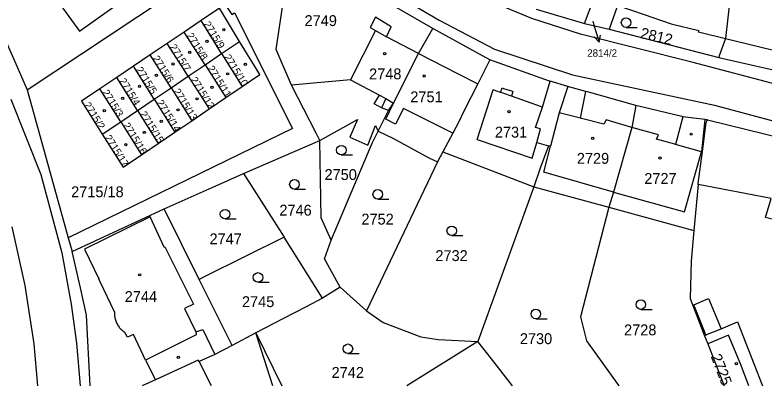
# Model space of a CAD drawing. Extents: x -527335 to -526256, y -1079142 to -1077836.
# Drawn here: x -527116.6 to -526999.4, y -1079141.5 to -1079083.6 of the extents above; entities that cross this region are included whole.
import ezdxf

# ---------------------------------------------------------------- set-up
doc = ezdxf.new("R2010")
doc.units = 0
for name, color, linetype in [('Hranice parcel', 7, 'Continuous'), ('Parcelní čísla', 7, 'Continuous'), ('Pop  PČ popisy', 7, 'Continuous'), ('Vnitřní kresba', 7, 'Continuous'), ('Značky budov', 7, 'Continuous'), ('Značky kultur', 7, 'Continuous')]:
    doc.layers.add(name, color=color, linetype=linetype)

msp = doc.modelspace()

# ---------------------------------------------------------------- linework, layer by layer
at = {"layer": 'Hranice parcel'}
for p, q in [((-527027.56, -1079084.87), (-527026.14, -1079080.97)), ((-527035.15, -1079082.66), (-527027.56, -1079084.87)), ((-527022.5, -1079082.36), (-527023.73, -1079085.78)), ((-527087.52, -1079084.42), (-527090.18, -1079086.21)), ((-527084.33, -1079089.58), (-527087.52, -1079084.42)), ((-527027.56, -1079084.87), (-527023.73, -1079085.78)), ((-527090.18, -1079086.21), (-527092.83, -1079087.99)), ((-527086.93, -1079091.34), (-527090.18, -1079086.21)), ((-527053.53, -1079089.58), (-527051.3, -1079085.65)), ((-527042.41, -1079090.54), (-527051.3, -1079085.65)), ((-527023.73, -1079085.78), (-527006.59, -1079090.18)), ((-527084.33, -1079089.58), (-527081.51, -1079087.68)), ((-527092.83, -1079087.99), (-527095.49, -1079089.78)), ((-527089.56, -1079093.11), (-527092.83, -1079087.99)), ((-527095.49, -1079089.78), (-527098.1, -1079091.54)), ((-527092.24, -1079094.93), (-527095.49, -1079089.78)), ((-527086.93, -1079091.34), (-527084.33, -1079089.58)), ((-527084.33, -1079089.58), (-527081.13, -1079094.75)), ((-527089.56, -1079093.11), (-527086.93, -1079091.34)), ((-527086.93, -1079091.34), (-527083.68, -1079096.47)), ((-527098.1, -1079091.54), (-527100.72, -1079093.3)), ((-527094.86, -1079096.7), (-527098.1, -1079091.54)), ((-527100.72, -1079093.3), (-527103.37, -1079095.09)), ((-527097.49, -1079098.47), (-527100.72, -1079093.3)), ((-527092.24, -1079094.93), (-527089.56, -1079093.11)), ((-527089.56, -1079093.11), (-527086.28, -1079098.23)), ((-527083.68, -1079096.47), (-527081.13, -1079094.75)), ((-527114.75, -1079095.26), (-527108.32, -1079118.4)), ((-527100.12, -1079100.24), (-527103.37, -1079095.09)), ((-527094.86, -1079096.7), (-527092.24, -1079094.93)), ((-527092.24, -1079094.93), (-527089, -1079100.07)), ((-527097.49, -1079098.47), (-527094.86, -1079096.7)), ((-527094.86, -1079096.7), (-527091.63, -1079101.85)), ((-527086.28, -1079098.23), (-527083.68, -1079096.47)), ((-527089, -1079100.07), (-527086.28, -1079098.23)), ((-527100.12, -1079100.24), (-527097.49, -1079098.47)), ((-527097.49, -1079098.47), (-527094.26, -1079103.63)), ((-527102.99, -1079102.18), (-527100.12, -1079100.24)), ((-527100.12, -1079100.24), (-527096.87, -1079105.39)), ((-527091.63, -1079101.85), (-527089, -1079100.07)), ((-527094.26, -1079103.63), (-527091.63, -1079101.85)), ((-527096.87, -1079105.39), (-527094.26, -1079103.63)), ((-527080.91, -1079108.31), (-527068.95, -1079103.19)), ((-527049.72, -1079104.95), (-527050.56, -1079106.52)), ((-527049.72, -1079104.95), (-527035.52, -1079110.39)), ((-527050.56, -1079106.52), (-527061.66, -1079129.77)), ((-527080.91, -1079108.31), (-527074.57, -1079118.3)), ((-527009.82, -1079110.06), (-527010.5, -1079117.24)), ((-527035.52, -1079110.39), (-527044.28, -1079134.58)), ((-527035.52, -1079110.39), (-527023.76, -1079113.6)), ((-527023.76, -1079113.6), (-527010.5, -1079117.24)), ((-527107.73, -1079120.51), (-527093.31, -1079113.86)), ((-527087.83, -1079124.87), (-527093.31, -1079113.86)), ((-527068.54, -1079127.79), (-527074.57, -1079118.3)), ((-527108.32, -1079118.4), (-527107.73, -1079120.51)), ((-527082.7, -1079135.19), (-527087.83, -1079124.87)), ((-527065.77, -1079126.11), (-527068.54, -1079127.79)), ((-527061.66, -1079129.77), (-527065.77, -1079126.11)), ((-527078.96, -1079133.24), (-527082.7, -1079135.19)), ((-527076.3, -1079141.53), (-527078.96, -1079133.24)), ((-527078.96, -1079133.24), (-527074.91, -1079141.53)), ((-527044.28, -1079134.58), (-527055.39, -1079141.53)), ((-527042.15, -1079137.3), (-527044.28, -1079134.58)), ((-527008.8, -1079133.68), (-527008.31, -1079134.94)), ((-527008.31, -1079134.94), (-527005.73, -1079141.53)), ((-527038.84, -1079141.53), (-527042.15, -1079137.3))]:
    msp.add_line(p, q, dxfattribs=at)
for points in [[(-527175.94, -1079018.95), (-527174.51, -1079020.99), (-527170.88, -1079024.19), (-527166.19, -1079028.15), (-527156.94, -1079036.03), (-527151.99, -1079040.51), (-527144.47, -1079048.33), (-527131.02, -1079065.08), (-527128.12, -1079070.27), (-527126.15, -1079072.81), (-527121.46, -1079080.6), (-527119.15, -1079085.27), (-527115.79, -1079092.86), (-527114.75, -1079095.26)], [(-527117.52, -1079070.91), (-527112.81, -1079077.42), (-527111.7, -1079078.95), (-527106.54, -1079086.08), (-527097.38, -1079079.49), (-527102.75, -1079072.09), (-527104.98, -1079069.03), (-527108.4, -1079064.32), (-527113.48, -1079057.33), (-527115.7, -1079054.27), (-527119.42, -1079049.14)], [(-527017.49, -1079069.84), (-527011.34, -1079074.38), (-527006.77, -1079078.58), (-527004.82, -1079080.69), (-527005.52, -1079087.25)], [(-527073.4, -1079094.53), (-527075.8, -1079088.93), (-527073.64, -1079074.56), (-527071.09, -1079071.9)], [(-527051.3, -1079085.65), (-527059.51, -1079080.86), (-527065.39, -1079076.64), (-527071.09, -1079071.9)], [(-527114.75, -1079095.26), (-527093.11, -1079080.89), (-527091.79, -1079079.94), (-527087.05, -1079076.88), (-527082.75, -1079083.47), (-527082.32, -1079083.22), (-527073.26, -1079101.27), (-527108.32, -1079118.4)], [(-527081.51, -1079087.68), (-527084.66, -1079082.49), (-527087.52, -1079084.42)], [(-527022.39, -1079082.06), (-527018.27, -1079083.48), (-527014.05, -1079084.93), (-527009.72, -1079085.95), (-527009.78, -1079086.18), (-527009.52, -1079086.24), (-527005.52, -1079087.25)], [(-527053.53, -1079089.58), (-527058.56, -1079086.96), (-527057.82, -1079085.39), (-527060.29, -1079083.91), (-527061.12, -1079085.5), (-527060.26, -1079085.95), (-527064.15, -1079093.71), (-527073.4, -1079094.53)], [(-527081.13, -1079094.75), (-527078.36, -1079092.87), (-527081.51, -1079087.68)], [(-527005.52, -1079087.25), (-527006.5, -1079089.94), (-527006.59, -1079090.18)], [(-527059.85, -1079101.72), (-527058.21, -1079098.49), (-527057.45, -1079097.35), (-527053.53, -1079089.58)], [(-527006.59, -1079090.18), (-526994.63, -1079092.92), (-526991.9, -1079089.68)], [(-527042.41, -1079090.54), (-527044.26, -1079094.33), (-527046.46, -1079098.6), (-527047.21, -1079100.23), (-527048.16, -1079102.02), (-527049.72, -1079104.95)], [(-527030.16, -1079094.72), (-527032.95, -1079093.92), (-527033.07, -1079093.88), (-527042.41, -1079090.54)], [(-527068.95, -1079103.19), (-527069.52, -1079102.03), (-527073.4, -1079094.53)], [(-527030.16, -1079094.72), (-527031.52, -1079098.85), (-527032.88, -1079104.05), (-527033.22, -1079104), (-527034.51, -1079107.51), (-527035.52, -1079110.39)], [(-527019.56, -1079097.69), (-527027.13, -1079095.57), (-527027.36, -1079095.5), (-527030.01, -1079094.76), (-527030.16, -1079094.72)], [(-527103.37, -1079095.09), (-527106.24, -1079097.02), (-527102.99, -1079102.18)], [(-527019.56, -1079097.69), (-527020.17, -1079101.16), (-527023.05, -1079111.23), (-527023.76, -1079113.6)], [(-527008.36, -1079099.95), (-527008.58, -1079099.92), (-527008.77, -1079099.9), (-527012.21, -1079099.46), (-527012.36, -1079099.44), (-527019.56, -1079097.69)], [(-527068.95, -1079103.19), (-527063.07, -1079099.9), (-527064.28, -1079102.63), (-527061.45, -1079103.88), (-527060.28, -1079100.83), (-527059.85, -1079101.72)], [(-527009.82, -1079110.06), (-527009.8, -1079109.91), (-527009.1, -1079104.91), (-527008.55, -1079100.34), (-527008.36, -1079099.95)], [(-527008.36, -1079099.95), (-526996.25, -1079102.89), (-526987.44, -1079105.14), (-526984.58, -1079106.98)], [(-527067.18, -1079118.75), (-527060.79, -1079103.58), (-527059.85, -1079101.72)], [(-527059.85, -1079101.72), (-527057.47, -1079102.88), (-527051.9, -1079105.88), (-527050.56, -1079106.52)], [(-527102.99, -1079102.18), (-527099.75, -1079107.33), (-527096.87, -1079105.39)], [(-527067.18, -1079118.75), (-527068.78, -1079115.24), (-527068.95, -1079103.19)], [(-527093.31, -1079113.86), (-527085.79, -1079110.53), (-527080.91, -1079108.31)], [(-526971.93, -1079115.94), (-526976.33, -1079115.57), (-526988.12, -1079117.78), (-526988.51, -1079117.72), (-526989.62, -1079117.54), (-526999.27, -1079115.18), (-526998.37, -1079112.24), (-527009.82, -1079110.06)], [(-527023.76, -1079113.6), (-527028.19, -1079130.73), (-527027.25, -1079134.48), (-527022.21, -1079141.53)], [(-527074.57, -1079118.3), (-527086.94, -1079124.43), (-527087.83, -1079124.87)], [(-527010.5, -1079117.24), (-527010.9, -1079122.03), (-527011.07, -1079127.87), (-527008.8, -1079133.68)], [(-527065.77, -1079126.11), (-527068.26, -1079121.64), (-527067.18, -1079118.75)], [(-527104.87, -1079141.53), (-527105.47, -1079130.49), (-527106.38, -1079126.22), (-527107.73, -1079120.51)], [(-527068.54, -1079127.79), (-527071.12, -1079129.14), (-527074.77, -1079131.05), (-527078.96, -1079133.24)], [(-527061.66, -1079129.77), (-527059.09, -1079131.59), (-527053.17, -1079133.84), (-527050.44, -1079134.25), (-527044.28, -1079134.58)], [(-527008.8, -1079133.68), (-527008.59, -1079133.56), (-527006.18, -1079132.58), (-527003.65, -1079131.52), (-526999.76, -1079141.53)], [(-527001.89, -1079141.53), (-527003.17, -1079138.09), (-527005.05, -1079133.57), (-527008.31, -1079134.94)], [(-527082.7, -1079135.19), (-527085.39, -1079136.6), (-527087.84, -1079137.7), (-527088, -1079137.51), (-527094.65, -1079140.58), (-527096.75, -1079141.53)]]:
    msp.add_lwpolyline(points, dxfattribs=at)
at = {"layer": 'Pop  PČ popisy'}
for p, q in [((-527026.27, -1079084.53), (-527026.16, -1079084.91)), ((-527026.16, -1079084.91), (-527025.28, -1079087.78)), ((-527025.28, -1079087.78), (-527026.05, -1079086.97)), ((-527025.28, -1079087.78), (-527025.1, -1079086.68))]:
    msp.add_line(p, q, dxfattribs=at)
at = {"layer": 'Vnitřní kresba'}
for p, q in [((-527058.51, -1079079.53), (-527050.31, -1079084.34)), ((-527035.83, -1079084.12), (-527043.03, -1079081.09)), ((-527028.2, -1079086.55), (-527035.83, -1079084.12)), ((-527050.31, -1079084.34), (-527041.68, -1079088.91)), ((-527060.26, -1079085.95), (-527058.56, -1079086.96)), ((-527010.79, -1079090.93), (-527028.2, -1079086.55)), ((-527005.52, -1079087.25), (-526998.21, -1079088.98)), ((-527041.68, -1079088.91), (-527029.48, -1079092.89)), ((-527053.53, -1079089.58), (-527047.35, -1079092.75)), ((-526994.16, -1079095.3), (-527010.79, -1079090.93)), ((-527047.35, -1079092.75), (-527044.26, -1079094.33)), ((-527029.48, -1079092.89), (-527007.27, -1079097.63)), ((-527064.15, -1079093.71), (-527059.66, -1079096.06)), ((-527034.16, -1079097.97), (-527032.95, -1079093.92)), ((-527044.36, -1079103.01), (-527041.85, -1079095.25)), ((-527040.71, -1079095.64), (-527041.85, -1079095.25)), ((-527040.71, -1079095.64), (-527040.46, -1079094.96)), ((-527040.46, -1079095.73), (-527040.71, -1079095.64)), ((-527040.46, -1079094.96), (-527040.23, -1079095.03)), ((-527039.29, -1079096.14), (-527040.46, -1079095.73)), ((-527040.23, -1079095.03), (-527039.01, -1079095.42)), ((-527038.77, -1079095.5), (-527039.02, -1079096.23)), ((-527039.01, -1079095.42), (-527038.77, -1079095.5)), ((-527028.22, -1079099.7), (-527027.36, -1079095.5)), ((-527117.32, -1079096.72), (-527112.58, -1079108.47)), ((-527060.45, -1079097.43), (-527059.66, -1079096.06)), ((-527059.66, -1079096.06), (-527058.66, -1079096.58)), ((-527058.66, -1079096.58), (-527059.35, -1079098.07)), ((-527058.66, -1079096.58), (-527057.45, -1079097.35)), ((-527039.02, -1079096.23), (-527039.29, -1079096.14)), ((-527034.3, -1079097.92), (-527039.02, -1079096.23)), ((-527059.35, -1079098.07), (-527060.45, -1079097.43)), ((-527058.21, -1079098.49), (-527059.35, -1079098.07)), ((-527058.65, -1079099.84), (-527057.45, -1079097.35)), ((-527055.88, -1079098.14), (-527057.14, -1079100.6)), ((-527048.16, -1079102.02), (-527055.88, -1079098.14)), ((-527035.22, -1079101.14), (-527034.16, -1079097.97)), ((-527034.3, -1079097.92), (-527034.16, -1079097.97)), ((-527007.27, -1079097.63), (-526996.46, -1079100.53)), ((-527031.35, -1079098.89), (-527031.52, -1079098.85)), ((-527028.22, -1079099.7), (-527031.35, -1079098.89)), ((-527012.21, -1079099.46), (-527013.34, -1079103.8)), ((-527057.14, -1079100.6), (-527058.65, -1079099.84)), ((-527028.07, -1079099.74), (-527028.22, -1079099.7)), ((-527024.55, -1079100.64), (-527028.07, -1079099.74)), ((-527024.19, -1079099.96), (-527024.55, -1079100.64)), ((-527020.17, -1079101.16), (-527024.19, -1079099.96)), ((-527008.77, -1079099.9), (-527009.28, -1079104.94)), ((-527034.45, -1079101.35), (-527035.22, -1079101.14)), ((-527035.06, -1079103.47), (-527034.45, -1079101.35)), ((-527016, -1079102.26), (-527020.17, -1079101.16)), ((-527044.36, -1079103.01), (-527035.77, -1079105.93)), ((-527016.3, -1079102.96), (-527016, -1079102.26)), ((-527013.46, -1079103.76), (-527016.3, -1079102.96)), ((-527035.77, -1079105.93), (-527035.06, -1079103.47)), ((-527035.06, -1079103.47), (-527033.22, -1079104)), ((-527033.92, -1079108.11), (-527032.88, -1079104.05)), ((-527013.34, -1079103.8), (-527013.46, -1079103.76)), ((-527009.28, -1079104.94), (-527013.34, -1079103.8)), ((-527011.92, -1079114.33), (-527009.28, -1079104.94)), ((-527009.28, -1079104.94), (-527009.1, -1079104.91)), ((-527112.58, -1079108.47), (-527109.31, -1079120.7)), ((-527023.05, -1079111.23), (-527033.92, -1079108.11)), ((-527023.05, -1079111.23), (-527011.92, -1079114.33)), ((-527095.53, -1079115.09), (-527105.76, -1079120.14)), ((-527093.31, -1079119.84), (-527095.53, -1079115.09)), ((-527115.04, -1079125.83), (-527117.11, -1079116.67)), ((-527105.76, -1079120.14), (-527103.56, -1079124.79)), ((-527093.31, -1079119.84), (-527093.19, -1079119.8)), ((-527093.19, -1079119.8), (-527088.74, -1079128.74)), ((-527109.31, -1079120.7), (-527107.85, -1079128.75)), ((-527103.34, -1079125.25), (-527103.56, -1079124.79)), ((-527101.06, -1079129.97), (-527103.34, -1079125.25)), ((-527113.64, -1079134.93), (-527115.04, -1079125.83)), ((-527107.85, -1079128.75), (-527107.02, -1079134.86)), ((-527088.74, -1079128.74), (-527090.12, -1079129.4)), ((-527010.5, -1079128.87), (-527008.19, -1079127.87)), ((-527008.59, -1079133.56), (-527010.5, -1079128.87)), ((-527008.19, -1079127.87), (-527006.18, -1079132.58)), ((-527090.12, -1079129.4), (-527088.37, -1079133.08)), ((-527099.07, -1079133.93), (-527099.45, -1079133.15)), ((-527098.09, -1079133.47), (-527099.07, -1079133.93)), ((-527096.23, -1079137.48), (-527098.09, -1079133.47)), ((-527088.29, -1079133.55), (-527096.23, -1079137.48)), ((-527088.37, -1079133.08), (-527087.25, -1079132.71)), ((-527088.37, -1079133.08), (-527088.29, -1079133.55)), ((-527087.25, -1079132.71), (-527085.39, -1079136.6)), ((-527113.06, -1079141.53), (-527113.64, -1079134.93)), ((-527107.02, -1079134.86), (-527106.47, -1079141.53)), ((-527096.23, -1079137.48), (-527094.65, -1079140.58)), ((-527085.91, -1079141.53), (-527087.84, -1079137.7))]:
    msp.add_line(p, q, dxfattribs=at)
msp.add_lwpolyline([(-527101.06, -1079129.97), (-527101.07, -1079130.13), (-527101.07, -1079130.28), (-527101.07, -1079130.44), (-527101.06, -1079130.6), (-527101.04, -1079130.75), (-527101.02, -1079130.91), (-527100.98, -1079131.06), (-527100.95, -1079131.21), (-527100.9, -1079131.36), (-527100.84, -1079131.51), (-527100.78, -1079131.65), (-527100.72, -1079131.79), (-527100.64, -1079131.93), (-527100.56, -1079132.07), (-527100.47, -1079132.2), (-527100.38, -1079132.32), (-527100.28, -1079132.45), (-527100.18, -1079132.56), (-527100.07, -1079132.67), (-527099.95, -1079132.78), (-527099.84, -1079132.88), (-527099.71, -1079132.98), (-527099.58, -1079133.07), (-527099.45, -1079133.15)], dxfattribs=at)
at = {"layer": 'Značky budov'}
for centre in [(-527083.98, -1079085.84), (-527086.63, -1079087.65), (-527089.31, -1079089.38), (-527058.84, -1079089.61), (-527091.95, -1079091.2), (-527080.62, -1079091.27), (-527094.54, -1079092.99), (-527083.4, -1079092.75), (-527052.66, -1079093.07), (-527097.18, -1079094.72), (-527085.83, -1079094.84), (-527099.79, -1079096.57), (-527088.18, -1079096.65), (-527102.68, -1079098.52), (-527091.16, -1079098.37), (-527039.39, -1079098.65), (-527093.77, -1079100.18), (-527096.42, -1079101.91), (-527026.3, -1079102.83), (-527010.9, -1079102.18), (-527099.31, -1079103.82), (-527015.76, -1079105.92), (-527097.14, -1079124.16), (-527091.12, -1079137.05), (-527003.82, -1079138.05)]:
    msp.add_circle(centre, 0.175, dxfattribs=at)
at = {"layer": 'Značky kultur'}
for p, q in [((-527021.07, -1079085.49), (-527019.32, -1079085.49)), ((-527065.61, -1079105.43), (-527063.86, -1079105.43)), ((-527072.94, -1079110.77), (-527071.19, -1079110.77)), ((-527059.91, -1079112.34), (-527058.16, -1079112.34)), ((-527083.79, -1079115.43), (-527082.04, -1079115.43)), ((-527048.34, -1079118.04), (-527046.59, -1079118.04)), ((-527078.64, -1079125.32), (-527076.89, -1079125.32)), ((-527018.77, -1079129.56), (-527017.02, -1079129.56)), ((-527035.19, -1079131.02), (-527033.44, -1079131.02)), ((-527064.58, -1079136.47), (-527062.83, -1079136.47))]:
    msp.add_line(p, q, dxfattribs=at)
for centre in [(-527021.07, -1079084.74), (-527065.61, -1079104.68), (-527072.94, -1079110.02), (-527059.91, -1079111.59), (-527083.79, -1079114.68), (-527048.34, -1079117.29), (-527078.64, -1079124.57), (-527018.77, -1079128.81), (-527035.19, -1079130.27), (-527064.58, -1079135.72)]:
    msp.add_circle(centre, 0.75, dxfattribs=at)

# ---------------------------------------------------------------- texts
at = {"layer": 'Parcelní čísla'}
for s, height, p in [('2749', 1.7, (-527071.36, -1079085.28)), ('2814/2', 1.14, (-527027.15, -1079090.07)), ('2748', 1.7, (-527061.27, -1079093.61)), ('2751', 1.7, (-527054.82, -1079097.19)), ('2731', 1.7, (-527041.6, -1079102.71)), ('2729', 1.7, (-527028.78, -1079106.81)), ('2750', 1.7, (-527068.24, -1079109.34)), ('2727', 1.7, (-527018.23, -1079109.95)), ('2715/18', 1.7, (-527107.87, -1079112.03)), ('2746', 1.7, (-527075.3, -1079114.91)), ('2752', 1.7, (-527062.47, -1079116.31)), ('2747', 1.7, (-527086.23, -1079119.39)), ('2732', 1.7, (-527050.9, -1079122.01)), ('2744', 1.7, (-527099.49, -1079128.41)), ('2745', 1.7, (-527081.15, -1079129.21)), ('2728', 1.7, (-527021.39, -1079133.62)), ('2730', 1.7, (-527037.69, -1079134.99)), ('2742', 1.7, (-527067.13, -1079140.27))]:
    msp.add_text(s, height=height, dxfattribs=at).set_placement(p)
for s, height, rotation, p in [('2715/9', 1.14, 302, (-527087.19, -1079084.98)), ('2715/8', 1.14, 302, (-527089.85, -1079086.77)), ('2812', 1.7, 347, (-527018.95, -1079087.14)), ('2715/7', 1.14, 302, (-527092.5, -1079088.55)), ('2715/6', 1.14, 302, (-527095.16, -1079090.34)), ('2715/10', 1.14, 302, (-527084, -1079090.14)), ('2715/5', 1.14, 302, (-527097.77, -1079092.1)), ('2715/11', 1.14, 302, (-527086.6, -1079091.9)), ('2715/4', 1.14, 302, (-527100.39, -1079093.86)), ('2715/12', 1.14, 302, (-527089.23, -1079093.67)), ('2715/3', 1.14, 302, (-527103.04, -1079095.65)), ('2715/13', 1.14, 302, (-527091.91, -1079095.49)), ('2715/2', 1.14, 302, (-527105.92, -1079097.61)), ('2715/14', 1.14, 302, (-527094.53, -1079097.26)), ('2715/15', 1.14, 302, (-527097.16, -1079099.03)), ('2715/16', 1.14, 302, (-527099.79, -1079100.8)), ('2715/17', 1.14, 302, (-527102.66, -1079102.74)), ('2725', 1.7, 291, (-527007.86, -1079136.9))]:
    msp.add_text(s, height=height, rotation=rotation, dxfattribs=at).set_placement(p)

doc.saveas('drawing.dxf')
